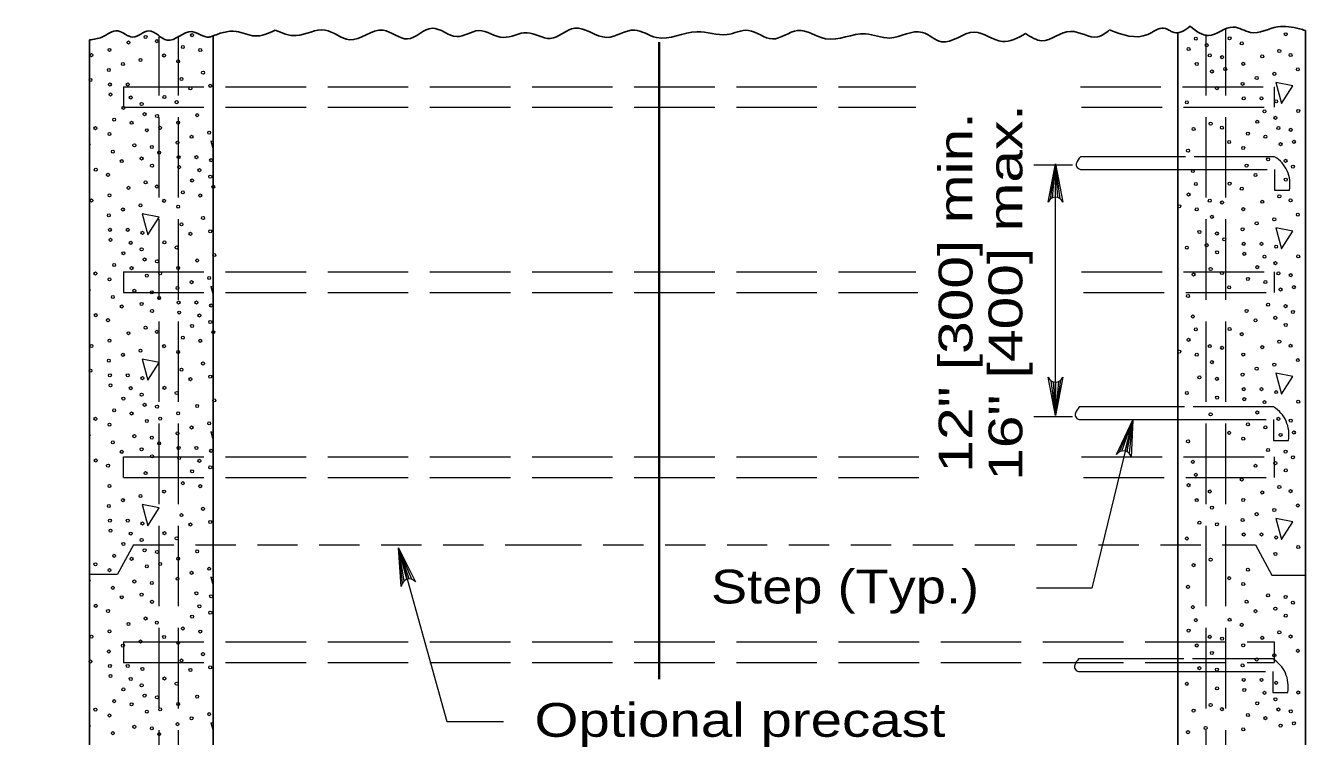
# Model space of a CAD drawing. Extents: x 1329.9 to 1363.9, y 715.5 to 737.5.
# Drawn here: x 1340.22 to 1346.13, y 725.4 to 728.68 of the extents above; entities that cross this region are included whole.
import ezdxf
from ezdxf.enums import TextEntityAlignment as Align

# ---------------------------------------------------------------- set-up
doc = ezdxf.new("R2010")
doc.units = 0
doc.header["$LTSCALE"] = 0.062
doc.linetypes.add('LONG_DASHED', pattern=[7.5, 6, -1.5])
doc.linetypes.add('MEDIUM_DASHED', pattern=[4.5, 3, -1.5])
doc.layers.add('1', color=7, linetype='Continuous', lineweight=13)

msp = doc.modelspace()

# ---------------------------------------------------------------- linework, layer by layer
at = {"layer": '1', "lineweight": 25}
for p, q in [((1345.54217, 721.19308), (1345.54217, 728.652)), ((1341.08508, 728.63108), (1341.08508, 723.71042))]:
    msp.add_line(p, q, dxfattribs=at)
at = {"layer": '1', "linetype": 'LONG_DASHED'}
for p, q in [((1345.76417, 718.91875), (1345.76417, 728.66458)), ((1340.83683, 718.91875), (1340.83683, 728.63117)), ((1340.92608, 718.91875), (1340.92608, 728.63467)), ((1345.67267, 718.91875), (1345.67267, 728.64083)), ((1340.67083, 728.39908), (1340.67083, 728.30408)), ((1340.67083, 728.39908), (1344.33208, 728.39908)), ((1345.09167, 728.39908), (1345.98667, 728.39908)), ((1345.98667, 728.39908), (1345.98667, 728.30408)), ((1340.67083, 728.30408), (1344.33208, 728.30408)), ((1345.09675, 728.30408), (1345.98667, 728.30408)), ((1345.98917, 728.07533), (1345.57767, 728.07533)), ((1340.67083, 727.54417), (1340.67083, 727.44925)), ((1340.67083, 727.54417), (1344.33208, 727.54417)), ((1345.09675, 727.54417), (1345.98667, 727.54417)), ((1345.98667, 727.54417), (1345.98667, 727.44925)), ((1340.67083, 727.44925), (1344.34158, 727.44925)), ((1345.10625, 727.44925), (1345.98667, 727.44925)), ((1345.98425, 726.91967), (1345.57275, 726.91967)), ((1340.67083, 726.59433), (1340.67083, 726.68933)), ((1340.67083, 726.68933), (1344.34617, 726.68933)), ((1345.09675, 726.68933), (1345.98667, 726.68933)), ((1345.98667, 726.68933), (1345.98667, 726.59433)), ((1340.67083, 726.59433), (1344.34617, 726.59433)), ((1345.10625, 726.59433), (1345.98667, 726.59433)), ((1340.67083, 725.8345), (1345.98667, 725.8345)), ((1340.67083, 725.8345), (1340.67083, 725.7395)), ((1345.98667, 725.8345), (1345.98667, 725.7395)), ((1345.981, 725.75542), (1345.5695, 725.75542)), ((1340.67083, 725.7395), (1345.98667, 725.7395))]:
    msp.add_line(p, q, dxfattribs=at)
at = {"layer": '1', "lineweight": 35}
msp.add_line((1343.146, 728.60575), (1343.146, 725.66267), dxfattribs=at)
at = {"layer": '1'}
for p, q in [((1341.075, 728.14758), (1341.085, 728.10958)), ((1341.085, 728.14558), (1341.075, 728.14758)), ((1345.57767, 728.07533), (1345.09167, 728.07533)), ((1344.877, 728.03883), (1345.05592, 728.03883)), ((1344.95333, 727.88017), (1344.97683, 728.04325)), ((1344.96317, 727.88633), (1344.97683, 728.04325)), ((1344.97683, 726.87975), (1344.97683, 728.04325)), ((1344.97683, 727.88917), (1344.97683, 728.04325)), ((1344.98758, 727.8875), (1344.97683, 728.04325)), ((1344.99817, 727.882), (1344.97683, 728.04325)), ((1345.09167, 728.01675), (1345.5825, 728.01675)), ((1341.075, 727.47592), (1341.085, 727.43792)), ((1341.08508, 727.47392), (1341.075, 727.47592)), ((1344.95558, 727.041), (1344.97683, 726.87975)), ((1344.96608, 727.03558), (1344.97683, 726.87975)), ((1345.00042, 727.04292), (1344.97683, 726.87975)), ((1344.9905, 727.03675), (1344.97683, 726.87975)), ((1344.97683, 727.03392), (1344.97683, 726.87975)), ((1344.877, 726.87533), (1345.05592, 726.87533)), ((1345.57275, 726.91967), (1345.08675, 726.91967)), ((1345.08675, 726.86108), (1345.57758, 726.86108)), ((1345.33417, 726.8595), (1345.14442, 726.08183)), ((1345.27183, 726.71208), (1345.33417, 726.8595)), ((1345.28333, 726.71592), (1345.33417, 726.8595)), ((1345.29792, 726.71575), (1345.33417, 726.8595)), ((1345.3085, 726.71208), (1345.33417, 726.8595)), ((1345.318, 726.70483), (1345.33417, 726.8595)), ((1341.075, 726.80425), (1341.08508, 726.76617)), ((1341.08508, 726.80225), (1341.075, 726.80425)), ((1341.98075, 726.12367), (1341.94142, 726.26833)), ((1341.96817, 726.1165), (1341.94142, 726.26833)), ((1341.96008, 726.1075), (1341.94142, 726.26833)), ((1341.99167, 726.12567), (1341.94142, 726.26833)), ((1342.00342, 726.12392), (1341.94142, 726.26833)), ((1341.94142, 726.26833), (1342.16567, 725.466)), ((1341.075, 726.13267), (1341.085, 726.09458)), ((1341.085, 726.13067), (1341.075, 726.13267)), ((1345.14442, 726.08183), (1344.8885, 726.08183)), ((1345.5695, 725.75542), (1345.0835, 725.75542)), ((1345.0835, 725.69683), (1345.57433, 725.69683)), ((1341.075, 725.461), (1341.085, 725.42292)), ((1341.08508, 725.45908), (1341.075, 725.461)), ((1342.16567, 725.466), (1342.427, 725.466))]:
    msp.add_line(p, q, dxfattribs=at)
at = {"layer": '1', "linetype": 'MEDIUM_DASHED'}
for p, q in [((1340.71792, 726.28267), (1340.64358, 726.14642)), ((1340.71792, 726.28267), (1342.60142, 726.28267)), ((1342.60142, 726.28267), (1345.89992, 726.28267)), ((1345.89992, 726.28267), (1345.97642, 726.14242)), ((1340.51525, 726.14642), (1340.64358, 726.14642)), ((1345.97642, 726.14242), (1346.12992, 726.14242))]:
    msp.add_line(p, q, dxfattribs=at)
at = {"layer": '1', "lineweight": 25}
for points in [[(1346.13117, 728.65933), (1346.13117, 718.46475), (1340.5145, 718.46475), (1340.5145, 718.71467)], [(1340.21925, 723.71042), (1340.5145, 723.71042), (1340.5145, 728.61575)]]:
    msp.add_lwpolyline(points, dxfattribs=at)
at = {"layer": '1'}
for points in [[(1345.99517, 728.41908), (1346.02083, 728.32175), (1346.073, 728.40392)], [(1340.75783, 727.81175), (1340.78342, 727.71442), (1340.83575, 727.79658)], [(1345.99517, 727.7475), (1346.02083, 727.65008), (1346.073, 727.73225)], [(1340.75783, 727.14008), (1340.78342, 727.04275), (1340.83575, 727.12492)], [(1345.99517, 727.07575), (1346.02083, 726.9785), (1346.073, 727.06067)], [(1340.75783, 726.46842), (1340.78342, 726.37117), (1340.83575, 726.45333)], [(1345.99517, 726.40417), (1346.02083, 726.30675), (1346.073, 726.389)]]:
    msp.add_lwpolyline(points, close=True, dxfattribs=at)
for points in [[(1340.5145, 728.12608), (1340.5185, 728.13242), (1340.5145, 728.13308)], [(1344.94317, 727.86517), (1344.97683, 728.04325), (1345.0105, 727.86517)], [(1340.5145, 727.45442), (1340.5185, 727.46075), (1340.5145, 727.4615)], [(1345.0105, 727.05792), (1344.97683, 726.87975), (1344.94317, 727.05792)], [(1345.25792, 726.70017), (1345.33417, 726.8595), (1345.32667, 726.68658)], [(1340.5145, 726.78283), (1340.5185, 726.78908), (1340.5145, 726.78983)], [(1341.95408, 726.09017), (1341.94142, 726.26833), (1342.01975, 726.11217)], [(1340.51458, 726.11117), (1340.5185, 726.11742), (1340.51458, 726.11825)], [(1340.5145, 725.43958), (1340.5185, 725.44583), (1340.5145, 725.44667)]]:
    msp.add_lwpolyline(points, dxfattribs=at)
at = {"layer": '1', "linetype": 'LONG_DASHED'}
for points in [[(1345.5825, 728.01675), (1345.98917, 728.01675), (1345.98917, 727.92108), (1346.0575, 727.92108)], [(1345.57758, 726.86108), (1345.98425, 726.86108), (1345.98425, 726.76542), (1346.05258, 726.76542)], [(1345.57433, 725.69683), (1345.981, 725.69683), (1345.981, 725.60108), (1346.04933, 725.60108)]]:
    msp.add_lwpolyline(points, dxfattribs=at)
at = {"layer": '1'}
for centre in [(1340.98854, 728.63748), (1346.0406, 728.6418), (1340.69449, 728.60367), (1340.77332, 728.62902), (1340.82555, 728.60999), (1340.94545, 728.58279), (1345.62491, 728.62125), (1345.6754, 728.59131), (1345.78076, 728.62305), (1345.83728, 728.59948), (1340.52373, 728.54501), (1340.60684, 728.56942), (1340.75016, 728.5229), (1340.85891, 728.54378), (1341.02623, 728.56858), (1345.59145, 728.57318), (1345.68914, 728.54418), (1345.7465, 728.53596), (1345.9318, 728.53937), (1346.01063, 728.56472), (1346.06286, 728.54569), (1340.60372, 728.47667), (1340.66875, 728.50387), (1340.92404, 728.51658), (1341.03881, 728.46402), (1345.62914, 728.50428), (1345.69935, 728.4698), (1345.76104, 728.48071), (1345.84415, 728.50512), (1346.09622, 728.47948), (1340.51892, 728.43044), (1340.60885, 728.40956), (1340.69111, 728.40956), (1340.93948, 728.43497), (1341.07222, 728.40324), (1345.84103, 728.41237), (1345.90605, 728.43957), (1345.98747, 728.4586), (1340.61139, 728.36333), (1340.7048, 728.34973), (1340.86065, 728.35152), (1340.98061, 728.39143), (1345.72256, 728.39273), (1345.84616, 728.34526), (1345.92842, 728.34526), (1340.67134, 728.30165), (1340.75529, 728.31979), (1340.91717, 728.32796), (1345.58352, 728.32713), (1345.94211, 728.28543), (1345.99603, 728.33166), (1346.09796, 728.28722), (1340.62825, 728.24697), (1340.70903, 728.23275), (1340.76903, 728.27266), (1340.82639, 728.26443), (1340.92404, 728.23359), (1341.01169, 728.26785), (1345.69343, 728.2289), (1345.90865, 728.23735), (1345.9926, 728.25549), (1340.54171, 728.20796), (1340.60684, 728.18076), (1340.77924, 728.19828), (1340.84093, 728.20919), (1340.98594, 728.16805), (1341.06736, 728.18708), (1345.6146, 728.20355), (1345.74566, 728.20987), (1345.86556, 728.18267), (1345.94634, 728.16845), (1346.00634, 728.20836), (1346.0637, 728.20013), (1340.72161, 728.1282), (1340.80244, 728.1212), (1340.92092, 728.14085), (1345.77902, 728.14366), (1345.84415, 728.11646), (1346.01655, 728.13398), (1346.07824, 728.14489), (1340.62228, 728.09915), (1340.66341, 728.05561), (1340.75502, 728.06742), (1340.83612, 728.09462), (1340.92605, 728.07374), (1341.00831, 728.07374), (1341.07592, 728.06014), (1345.58886, 728.10375), (1345.95892, 728.0639), (1346.03975, 728.0569), (1340.54345, 728.0157), (1340.59997, 727.99214), (1340.80329, 728.03445), (1340.92858, 728.02751), (1341.022, 728.01391), (1345.61122, 728.00944), (1345.85959, 728.03485), (1345.90072, 727.99131), (1346.07343, 728.03032), (1340.69449, 727.93202), (1340.77332, 727.95738), (1340.82555, 727.93835), (1340.98854, 727.96583), (1341.07249, 727.98396), (1341.08623, 727.93684), (1345.62491, 727.94961), (1345.78076, 727.9514), (1345.83728, 727.92784), (1346.0406, 727.97015), (1340.52373, 727.87337), (1340.60684, 727.89777), (1340.85891, 727.87214), (1340.94545, 727.91115), (1341.02623, 727.89693), (1345.59145, 727.90153), (1345.68914, 727.87254), (1346.01063, 727.89308), (1346.06286, 727.87405), (1340.66875, 727.83223), (1340.75016, 727.85126), (1340.92404, 727.84493), (1345.54836, 727.84685), (1345.62914, 727.83263), (1345.7465, 727.86431), (1345.84415, 727.83347), (1345.9318, 727.86772), (1340.60372, 727.80503), (1340.93948, 727.76333), (1341.03881, 727.79238), (1345.69935, 727.79815), (1345.90605, 727.76793), (1345.98747, 727.78696), (1346.09622, 727.80784), (1340.60885, 727.73792), (1340.61139, 727.69169), (1340.69111, 727.73792), (1340.75872, 727.72432), (1340.98061, 727.71978), (1341.07222, 727.73159), (1345.64172, 727.72808), (1345.72256, 727.72108), (1345.75623, 727.6945), (1345.84103, 727.74073), (1340.7048, 727.67809), (1340.75529, 727.64814), (1340.86065, 727.67988), (1340.91717, 727.65631), (1345.58352, 727.65548), (1345.67513, 727.66729), (1345.7234, 727.63433), (1345.84616, 727.67362), (1345.92842, 727.67362), (1345.99603, 727.66002), (1340.62825, 727.57532), (1340.67134, 727.63001), (1340.76903, 727.60101), (1340.82639, 727.59279), (1341.01169, 727.5962), (1341.09051, 727.62156), (1345.84869, 727.62739), (1345.94211, 727.61379), (1345.9926, 727.58384), (1346.09796, 727.61558), (1340.54171, 727.53631), (1340.70903, 727.56111), (1340.77924, 727.52663), (1340.84093, 727.53754), (1340.92404, 727.56195), (1341.06736, 727.51544), (1345.6146, 727.5319), (1345.69343, 727.55726), (1345.74566, 727.53823), (1345.90865, 727.56571), (1346.00634, 727.53671), (1346.0637, 727.52849), (1340.60684, 727.50911), (1340.72161, 727.45655), (1340.92092, 727.4692), (1340.98594, 727.49641), (1345.77902, 727.47201), (1345.86556, 727.51102), (1345.94634, 727.49681), (1346.01655, 727.46233), (1346.07824, 727.47324), (1340.62228, 727.42751), (1340.75502, 727.39577), (1340.80244, 727.44956), (1340.83612, 727.42297), (1340.92605, 727.4021), (1341.00831, 727.4021), (1345.58886, 727.43211), (1340.54345, 727.34405), (1340.66341, 727.38396), (1340.80329, 727.3628), (1340.92858, 727.35586), (1341.022, 727.34226), (1341.07592, 727.38849), (1345.61122, 727.3378), (1345.85959, 727.36321), (1345.95892, 727.39225), (1346.03975, 727.38526), (1346.07343, 727.35867), (1340.59997, 727.32049), (1340.77332, 727.28573), (1340.98854, 727.29418), (1341.07249, 727.31232), (1345.62491, 727.27796), (1345.78076, 727.27975), (1345.90072, 727.31966), (1345.99233, 727.33147), (1346.0406, 727.2985), (1340.60684, 727.22612), (1340.69449, 727.26038), (1340.82555, 727.2667), (1340.94545, 727.2395), (1341.02623, 727.22528), (1341.08623, 727.26519), (1345.59145, 727.22988), (1345.83728, 727.25619), (1346.01063, 727.22143), (1340.52373, 727.20172), (1340.66875, 727.16058), (1340.75016, 727.17961), (1340.85891, 727.20049), (1340.92404, 727.17329), (1345.54836, 727.1752), (1345.62914, 727.16098), (1345.68914, 727.20089), (1345.7465, 727.19266), (1345.84415, 727.16182), (1345.9318, 727.19608), (1346.06286, 727.2024), (1340.60372, 727.13338), (1341.03881, 727.12073), (1345.69935, 727.12651), (1345.98747, 727.11531), (1346.09622, 727.13619), (1340.51892, 727.08715), (1340.60885, 727.06627), (1340.69111, 727.06627), (1340.75872, 727.05267), (1340.93948, 727.09168), (1340.98061, 727.04814), (1341.07222, 727.05995), (1345.64172, 727.05643), (1345.72256, 727.04944), (1345.84103, 727.06908), (1345.90605, 727.09628), (1340.61139, 727.02004), (1340.7048, 727.00644), (1340.86065, 727.00823), (1340.91717, 726.98467), (1345.58352, 726.98384), (1345.84616, 727.00197), (1345.92842, 727.00197), (1345.99603, 726.98837), (1340.67134, 726.95836), (1340.75529, 726.9765), (1340.76903, 726.92937), (1341.01169, 726.92456), (1341.09051, 726.94991), (1345.7234, 726.96268), (1345.84869, 726.95574), (1345.94211, 726.94214), (1346.09796, 726.94393), (1340.54171, 726.86467), (1340.62825, 726.90368), (1340.70903, 726.88946), (1340.82639, 726.92114), (1340.84093, 726.8659), (1340.92404, 726.8903), (1345.69343, 726.88561), (1345.90865, 726.89406), (1346.00634, 726.86507), (1340.60684, 726.83747), (1340.77924, 726.85498), (1340.98594, 726.82476), (1341.06736, 726.84379), (1345.86556, 726.83938), (1345.94634, 726.82516), (1346.0637, 726.85684), (1340.62228, 726.75586), (1340.72161, 726.78491), (1340.80244, 726.77791), (1340.83612, 726.75133), (1340.92092, 726.79756), (1345.58886, 726.76046), (1345.77902, 726.80037), (1345.84415, 726.77317), (1346.01655, 726.79068), (1346.07824, 726.8016), (1340.66341, 726.71232), (1340.75502, 726.72413), (1340.80329, 726.69116), (1340.92605, 726.73045), (1341.00831, 726.73045), (1341.07592, 726.71685), (1345.95892, 726.72061), (1346.03975, 726.71361), (1346.07343, 726.68703), (1340.54345, 726.67241), (1340.59997, 726.64884), (1340.92858, 726.68422), (1341.022, 726.67062), (1341.07249, 726.64067), (1345.61122, 726.66615), (1345.90072, 726.64802), (1345.99233, 726.65983), (1340.77332, 726.61409), (1340.94545, 726.56786), (1340.98854, 726.62254), (1345.62491, 726.60632), (1345.83728, 726.58454), (1346.0406, 726.62686), (1340.60684, 726.55448), (1340.85891, 726.52884), (1341.02623, 726.55364), (1345.59145, 726.55824), (1345.68914, 726.52925), (1345.9318, 726.52443), (1346.01063, 726.54979), (1346.06286, 726.53076), (1340.60372, 726.46174), (1340.66875, 726.48894), (1340.75016, 726.50797), (1345.62914, 726.48934), (1345.69935, 726.45486), (1345.84415, 726.49018), (1346.09622, 726.46454), (1340.60885, 726.39463), (1340.69111, 726.39463), (1340.93948, 726.42004), (1341.03881, 726.44909), (1345.84103, 726.39744), (1345.90605, 726.42464), (1345.98747, 726.44367), (1340.61139, 726.3484), (1340.7048, 726.33479), (1340.75872, 726.38103), (1340.86065, 726.33659), (1340.98061, 726.37649), (1341.07222, 726.3883), (1345.64172, 726.38479), (1345.72256, 726.37779), (1340.67134, 726.28672), (1340.75529, 726.30485), (1340.91717, 726.31302), (1345.58352, 726.31219), (1345.84616, 726.33033), (1345.92842, 726.33033), (1345.99603, 726.31673), (1346.09796, 726.27229), (1340.62825, 726.23203), (1340.70903, 726.21782), (1340.76903, 726.25772), (1340.82639, 726.2495), (1340.92404, 726.21866), (1341.01169, 726.25291), (1345.69343, 726.21396), (1345.9926, 726.24055), (1340.54171, 726.19302), (1340.60684, 726.16582), (1340.77924, 726.18334), (1340.84093, 726.19425), (1341.06736, 726.17214), (1345.6146, 726.18861), (1345.86556, 726.16773), (1340.72161, 726.11326), (1340.80244, 726.10627), (1340.92092, 726.12591), (1340.98594, 726.15311), (1345.77902, 726.12872), (1345.84415, 726.10152), (1340.62228, 726.08421), (1340.66341, 726.04067), (1340.75502, 726.05248), (1341.00831, 726.0588), (1341.07592, 726.0452), (1345.58886, 726.08881), (1345.95892, 726.04896), (1346.03975, 726.04197), (1340.54345, 726.00076), (1340.59997, 725.9772), (1340.80329, 726.01951), (1341.022, 725.99897), (1345.61122, 725.9945), (1345.85959, 726.01991), (1345.99233, 725.98818), (1346.07343, 726.01538), (1340.77332, 725.94244), (1340.82555, 725.92341), (1340.98854, 725.95089), (1341.07249, 725.96903), (1345.62491, 725.93467), (1345.78076, 725.93646), (1345.90072, 725.97637), (1346.0406, 725.95521), (1340.52373, 725.85843), (1340.60684, 725.88283), (1340.69449, 725.91709), (1340.94545, 725.89621), (1341.02623, 725.88199), (1345.59145, 725.88659), (1345.83728, 725.9129), (1346.01063, 725.87814), (1346.06286, 725.85911), (1340.66875, 725.81729), (1340.75016, 725.83632), (1340.85891, 725.8572), (1340.92404, 725.83), (1345.62914, 725.81769), (1345.68914, 725.8576), (1345.7465, 725.84937), (1345.84415, 725.81853), (1345.9318, 725.85279), (1340.51892, 725.74386), (1340.60372, 725.79009), (1340.93948, 725.74839), (1341.03881, 725.77744), (1345.69935, 725.78322), (1345.90605, 725.75299), (1345.98747, 725.77202), (1346.09622, 725.7929), (1340.60885, 725.72298), (1340.69111, 725.72298), (1340.75872, 725.70938), (1340.98061, 725.70485), (1341.07222, 725.71666), (1345.64172, 725.71314), (1345.72256, 725.70614), (1345.84103, 725.72579), (1340.61139, 725.67675), (1340.7048, 725.66315), (1340.75529, 725.6332), (1340.86065, 725.66494), (1340.91717, 725.64138), (1345.58352, 725.64055), (1345.84616, 725.65868), (1345.92842, 725.65868), (1345.99603, 725.64508), (1340.67134, 725.61507), (1340.76903, 725.58608), (1340.82639, 725.57785), (1341.01169, 725.58126), (1345.7234, 725.61939), (1345.84869, 725.61245), (1345.94211, 725.59885), (1345.9926, 725.5689), (1346.09796, 725.60064), (1340.54171, 725.52138), (1340.62825, 725.56039), (1340.70903, 725.54617), (1340.77924, 725.51169), (1340.84093, 725.52261), (1340.92404, 725.54701), (1345.6146, 725.51696), (1345.69343, 725.54232), (1345.74566, 725.52329), (1345.90865, 725.55077), (1346.00634, 725.52178), (1346.0637, 725.51355), (1340.60684, 725.49417), (1340.92092, 725.45427), (1340.98594, 725.48147), (1341.06736, 725.5005), (1345.86556, 725.49609), (1345.94634, 725.48187), (1346.01655, 725.44739), (1346.07824, 725.45831), (1340.62228, 725.41257), (1340.72161, 725.44162), (1340.80244, 725.43462), (1340.83612, 725.40804), (1345.58886, 725.41717), (1345.67027, 725.4362), (1345.84415, 725.42987)]:
    msp.add_ellipse(centre, major_axis=(0, 0.00718), ratio=0.944544, dxfattribs=at)
at = {"layer": '1', "linetype": 'LONG_DASHED'}
for centre in [(1345.92294, 727.94833), (1345.918, 726.79268), (1345.91479, 725.6284)]:
    msp.add_ellipse(centre, major_axis=(0, -0.14504), ratio=0.944544, start_param=1.3817766, end_param=2.6372404, dxfattribs=at)
at = {"layer": '1'}
for centre, major_axis, start_param, end_param in [((1344.97685, 727.85072), (0, 0.03844), 5.0978942, 7.4685073), ((1344.97685, 727.07233), (0, -0.03844), 5.0978942, 7.4685073), ((1345.28889, 726.67991), (0.03587, 0.01381), 6.0805799, 8.4511931), ((1341.99059, 726.08762), (0.01813, 0.0339), 5.8832924, 8.2539055)]:
    msp.add_ellipse(centre, major_axis=major_axis, ratio=0.944544, start_param=start_param, end_param=end_param, dxfattribs=at)
at = {"layer": '1', "lineweight": 25}
for points in [[(1340.5145, 728.61575), (1340.57183, 728.62858), (1340.6455, 728.65717), (1340.71442, 728.62825), (1340.78908, 728.65783), (1340.87292, 728.61433), (1340.98758, 728.65383), (1341.06767, 728.62883), (1341.07408, 728.63017)], [(1341.07408, 728.63017), (1341.19258, 728.65483), (1341.27733, 728.63375), (1341.37208, 728.66042)], [(1341.37208, 728.66042), (1341.46883, 728.63533), (1341.603, 728.66133), (1341.71575, 728.616), (1341.87042, 728.66058), (1341.98317, 728.62017), (1342.09792, 728.66942), (1342.21067, 728.63092), (1342.31225, 728.65867), (1342.42492, 728.627), (1342.53583, 728.64892), (1342.643, 728.62208), (1342.75583, 728.66942), (1342.90392, 728.62725), (1343.03167, 728.661), (1343.13317, 728.62633), (1343.3205, 728.6535), (1343.45933, 728.6405), (1343.55817, 728.65942), (1343.669, 728.62), (1343.78558, 728.6585), (1343.91508, 728.62108), (1344.09867, 728.64333), (1344.21142, 728.62433), (1344.36233, 728.65042), (1344.45092, 728.60692), (1344.60092, 728.6515), (1344.73042, 728.60817), (1344.83867, 728.64558)], [(1344.83867, 728.64558), (1344.91342, 728.61158), (1345.04667, 728.65517), (1345.1715, 728.62933), (1345.22667, 728.662)], [(1345.22667, 728.662), (1345.40275, 728.64092), (1345.47642, 728.6695), (1345.50742, 728.65725)], [(1345.50742, 728.65725), (1345.52467, 728.64933), (1345.59925, 728.67883)], [(1345.59925, 728.67883), (1345.68317, 728.63542), (1345.79783, 728.67492), (1345.87792, 728.64992), (1346.00283, 728.67592), (1346.10433, 728.66675), (1346.13117, 728.65933)]]:
    msp.add_spline(points, degree=3, dxfattribs=at)
at = {"layer": '1'}
for points in [[(1345.09167, 728.07533), (1345.07383, 728.04625), (1345.07383, 728.03083), (1345.09167, 728.01675)], [(1345.08675, 726.91967), (1345.06892, 726.89058), (1345.06892, 726.87517), (1345.08675, 726.86108)], [(1345.0835, 725.75542), (1345.06567, 725.72633), (1345.06567, 725.71092), (1345.0835, 725.69683)]]:
    msp.add_spline(points, degree=3, dxfattribs=at)

# ---------------------------------------------------------------- texts
at = {"layer": '1', "width": 1.3}
for s, p in [('16" [400] max.', (1344.82375, 727.44825)), ('12" [300] min.', (1344.593, 727.44829))]:
    msp.add_text(s, height=0.156, rotation=90, dxfattribs=at).set_placement(p, align=Align.CENTER)
at = {"layer": '1'}
for s, width, p in [('Step (Typ.)', 1.2, (1343.38533, 726.01183)), ('Optional precast', 1.25, (1342.57017, 725.39583))]:
    msp.add_text(s, height=0.156, dxfattribs=dict(at, width=width)).set_placement(p)

doc.saveas('drawing.dxf')
